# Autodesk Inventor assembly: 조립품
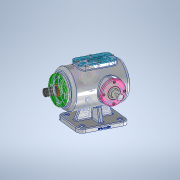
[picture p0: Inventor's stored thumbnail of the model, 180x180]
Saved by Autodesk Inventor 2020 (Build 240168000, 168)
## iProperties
Created: 2021-11
Part Number: 조립품
Document SubType Name: Assembly
Designer: USER
Author: USER
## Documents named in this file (14)
- C:\Users\USER\Desktop\711106V1042\조립품.iam
- C:\Users\USER\Desktop\711106V1042\본체.ipt
- C:\Users\USER\Desktop\711106V1042\베어링 6205.ipt
- 베어링 6205.ipt
- C:\Users\USER\Desktop\711106V1042\축 커버.ipt
- C:\Users\USER\Desktop\711106V1042\볼트 M4x0.7.ipt
- C:\Users\USER\Desktop\711106V1042\편심축.ipt
- C:\Users\USER\Desktop\711106V1042\상부커버.ipt
- C:\Users\USER\Desktop\711106V1042\육각머리볼트 M4.ipt
- C:\Users\USER\Desktop\711106V1042\오일실.ipt
- 오일실.ipt
- C:\Users\USER\Desktop\711106V1042\슬라이드 커버.ipt
- C:\Users\USER\Desktop\711106V1042\부시.ipt
- C:\Users\USER\Desktop\711106V1042\슬라이드.ipt
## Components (12 placed, 1 different names)
1. M4x0.7:2
2. M4x0.7:3
3. M4x0.7:4
4. M4x0.7:5
5. M4x0.7:10
6. M4x0.7:11
7. M4x0.7:12
8. M4x0.7:13
9. M4x0.7:9
10. M4x0.7:14
11. M4x0.7:15
12. M4x0.7:16
